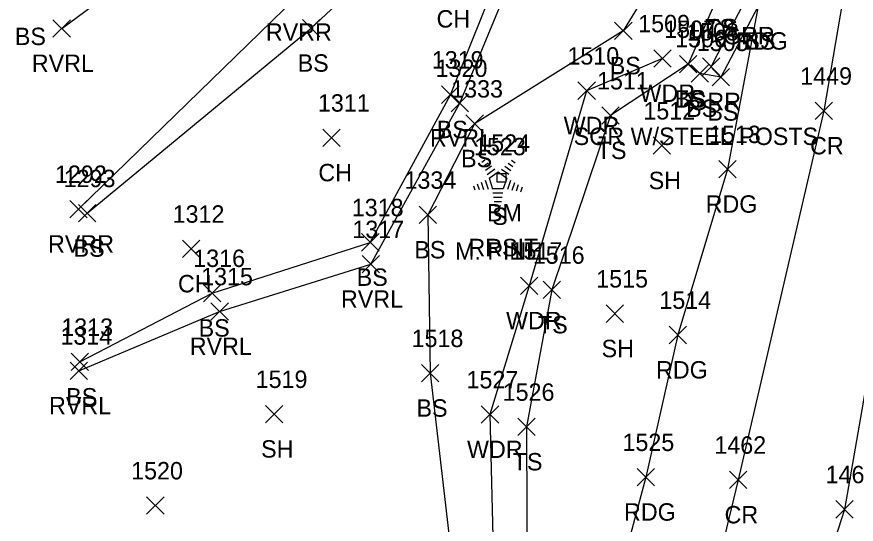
# Model space of a CAD drawing. Extents: x 1678553 to 1680768, y 787260 to 792325.
# Drawn here: x 1678590.7 to 1678687.1, y 787425.2 to 787483.5 of the extents above; entities that cross this region are included whole.
import ezdxf

# ---------------------------------------------------------------- set-up
doc = ezdxf.new("R2010")
doc.units = 0
for name, color, linetype in [('C_A', 7, 'Continuous'), ('C_C', 7, 'Continuous'), ('C_I', 7, 'Continuous'), ('CPBM', 7, 'Continuous'), ('L_A', 7, 'Continuous'), ('L_C', 7, 'Continuous'), ('L_I', 7, 'Continuous'), ('L_TIC', 7, 'Continuous'), ('LAWA', 7, 'Continuous'), ('LAWE', 7, 'Continuous'), ('LELB', 7, 'Continuous'), ('LTC', 7, 'Continuous'), ('P_A', 7, 'Continuous'), ('P_I', 7, 'Continuous'), ('P_TIC', 7, 'Continuous'), ('PEU', 7, 'Continuous'), ('PRC', 7, 'Continuous'), ('R_A', 7, 'Continuous'), ('R_C', 7, 'Continuous'), ('R_I', 7, 'Continuous'), ('R_TIC', 7, 'Continuous'), ('RGR', 7, 'Continuous')]:
    doc.layers.add(name, color=color, linetype=linetype)

msp = doc.modelspace()

# ---------------------------------------------------------------- linework, layer by layer
at = {"layer": 'CPBM'}
for p, q in [((1678645.899, 787464.531), (1678645.899, 787465.531)), ((1678645.899, 787465.531), (1678646.899, 787465.531)), ((1678646.402, 787465.032), (1678646.402, 787465.032)), ((1678646.402, 787465.032), (1678646.402, 787465.032)), ((1678646.899, 787465.531), (1678646.899, 787464.531)), ((1678646.899, 787464.531), (1678645.899, 787464.531))]:
    msp.add_line(p, q, dxfattribs=at)
at = {"layer": 'L_TIC'}
for points in [[(1678594.847, 787481.205), (1678596.847, 787483.205)], [(1678596.847, 787481.205), (1678594.847, 787483.205)], [(1678623.516, 787481.228), (1678625.516, 787483.228)], [(1678625.516, 787481.228), (1678623.516, 787483.228)], [(1678659.381, 787480.936), (1678661.381, 787482.936)], [(1678661.381, 787480.936), (1678659.381, 787482.936)], [(1678663.875, 787477.76), (1678665.875, 787479.76)], [(1678665.875, 787477.76), (1678663.875, 787479.76)], [(1678666.842, 787477.106), (1678668.842, 787479.106)], [(1678668.842, 787477.106), (1678666.842, 787479.106)], [(1678666.842, 787477.106), (1678668.842, 787479.106)], [(1678668.842, 787477.106), (1678666.842, 787479.106)], [(1678668.159, 787476.034), (1678670.159, 787478.034)], [(1678670.159, 787476.034), (1678668.159, 787478.034)], [(1678670.596, 787475.604), (1678672.596, 787477.604)], [(1678672.596, 787475.604), (1678670.596, 787477.604)], [(1678639.506, 787473.592), (1678641.506, 787475.592)], [(1678641.506, 787473.592), (1678639.506, 787475.592)], [(1678655.167, 787474.049), (1678657.167, 787476.049)], [(1678657.167, 787474.049), (1678655.167, 787476.049)], [(1678640.597, 787472.632), (1678642.597, 787474.632)], [(1678642.597, 787472.632), (1678640.597, 787474.632)], [(1678657.92, 787471.197), (1678659.92, 787473.197)], [(1678659.92, 787471.197), (1678657.92, 787473.197)], [(1678642.296, 787470.259), (1678644.296, 787472.259)], [(1678644.296, 787470.259), (1678642.296, 787472.259)], [(1678625.85, 787468.643), (1678627.85, 787470.643)], [(1678627.85, 787468.643), (1678625.85, 787470.643)], [(1678663.811, 787467.739), (1678665.811, 787469.739)], [(1678665.811, 787467.739), (1678663.811, 787469.739)], [(1678596.765, 787460.452), (1678598.765, 787462.452)], [(1678598.765, 787460.452), (1678596.765, 787462.452)], [(1678597.771, 787459.97), (1678599.771, 787461.97)], [(1678599.771, 787459.97), (1678597.771, 787461.97)], [(1678636.927, 787459.78), (1678638.927, 787461.78)], [(1678638.927, 787459.78), (1678636.927, 787461.78)], [(1678630.307, 787456.627), (1678632.307, 787458.627)], [(1678632.307, 787456.627), (1678630.307, 787458.627)], [(1678609.719, 787455.881), (1678611.719, 787457.881)], [(1678611.719, 787455.881), (1678609.719, 787457.881)], [(1678630.371, 787454.115), (1678632.371, 787456.115)], [(1678632.371, 787454.115), (1678630.371, 787456.115)], [(1678648.547, 787451.644), (1678650.547, 787453.644)], [(1678650.547, 787451.644), (1678648.547, 787453.644)], [(1678612.143, 787450.796), (1678614.143, 787452.796)], [(1678614.143, 787450.796), (1678612.143, 787452.796)], [(1678651.163, 787451.167), (1678653.163, 787453.167)], [(1678653.163, 787451.167), (1678651.163, 787453.167)], [(1678612.996, 787448.694), (1678614.996, 787450.694)], [(1678614.996, 787448.694), (1678612.996, 787450.694)], [(1678658.396, 787448.434), (1678660.396, 787450.434)], [(1678660.396, 787448.434), (1678658.396, 787450.434)], [(1678596.927, 787442.886), (1678598.927, 787444.886)], [(1678598.927, 787442.886), (1678596.927, 787444.886)], [(1678596.83, 787441.87), (1678598.83, 787443.87)], [(1678598.83, 787441.87), (1678596.83, 787443.87)], [(1678637.178, 787441.595), (1678639.178, 787443.595)], [(1678639.178, 787441.595), (1678637.178, 787443.595)], [(1678619.271, 787436.896), (1678621.271, 787438.896)], [(1678621.271, 787436.896), (1678619.271, 787438.896)], [(1678644.057, 787436.849), (1678646.057, 787438.849)], [(1678646.057, 787436.849), (1678644.057, 787438.849)], [(1678648.267, 787435.424), (1678650.267, 787437.424)], [(1678650.267, 787435.424), (1678648.267, 787437.424)], [(1678605.605, 787426.393), (1678607.605, 787428.393)], [(1678607.605, 787426.393), (1678605.605, 787428.393)]]:
    msp.add_lwpolyline(points, dxfattribs=at)
at = {"layer": 'LAWA'}
msp.add_lwpolyline([(1678664.875, 787478.76), (1678656.167, 787475.049), (1678649.547, 787452.644), (1678645.057, 787437.849), (1678645.533, 787417.534), (1678643.935, 787403.039), (1678640.142, 787385.556), (1678638.679, 787382.048), (1678636.341, 787358.012), (1678630.002, 787335.833), (1678617.261, 787305.351), (1678619.256, 787283.598)], dxfattribs=at)
at = {"layer": 'LAWE'}
for points in [[(1678597.83, 787442.87), (1678613.996, 787449.694), (1678631.371, 787455.115), (1678641.597, 787473.632), (1678648.099, 787489.375), (1678652.594, 787500.479), (1678670.341, 787510.611)], [(1678595.847, 787482.205), (1678614.765, 787496.203), (1678629.827, 787500.16), (1678637.075, 787496.761)], [(1678597.765, 787461.452), (1678622.801, 787485.788), (1678637.075, 787496.761)]]:
    msp.add_lwpolyline(points, dxfattribs=at)
at = {"layer": 'LELB'}
for points in [[(1678680.77, 787518.059), (1678676.295, 787498.712), (1678671.376, 787486.283), (1678667.842, 787478.106), (1678658.92, 787472.197), (1678652.163, 787452.167), (1678649.267, 787436.424), (1678649.323, 787416.121), (1678648.829, 787401.973), (1678646.777, 787382.688), (1678641.038, 787357.729), (1678634.181, 787333.529), (1678626.232, 787302.071), (1678622.908, 787282.585)], [(1678597.927, 787443.886), (1678613.143, 787451.796), (1678631.307, 787457.627), (1678640.506, 787474.592), (1678646.468, 787489.445), (1678651.341, 787501.275), (1678669.621, 787510.644)], [(1678670.341, 787510.611), (1678668.529, 787502.631), (1678666.357, 787491.771), (1678660.381, 787481.936), (1678643.296, 787471.259), (1678637.927, 787460.78), (1678638.178, 787442.595), (1678641.032, 787418.209), (1678640.004, 787400.912), (1678637.638, 787392.163), (1678640.142, 787385.556), (1678638.302, 787358.255), (1678630.002, 787335.833)], [(1678598.771, 787460.97), (1678624.516, 787482.228), (1678639.243, 787496.026)], [(1678675.858, 787484.768), (1678671.596, 787476.604), (1678669.159, 787477.034), (1678667.842, 787478.106)]]:
    msp.add_lwpolyline(points, dxfattribs=at)
at = {"layer": 'LTC'}
for p, q in [((1678644.116, 787466.838), (1678644.471, 787467.095)), ((1678647.515, 787467.078), (1678647.934, 787466.774)), ((1678644.326, 787466.372), (1678644.855, 787466.757)), ((1678644.536, 787465.907), (1678645.239, 787466.418)), ((1678644.745, 787465.441), (1678645.624, 787466.079)), ((1678646.401, 787466.033), (1678647.211, 787465.445)), ((1678646.773, 787466.382), (1678647.452, 787465.888)), ((1678647.144, 787466.73), (1678647.693, 787466.331)), ((1678644.97, 787464.986), (1678645.981, 787465.72)), ((1678644.97, 787464.986), (1678645.357, 787463.792)), ((1678645.981, 787465.72), (1678646.979, 787464.995)), ((1678646.979, 787464.995), (1678646.587, 787463.792)), ((1678643.149, 787464.117), (1678643.301, 787463.649)), ((1678643.604, 787464.334), (1678643.816, 787463.682)), ((1678644.06, 787464.55), (1678644.331, 787463.715)), ((1678644.515, 787464.767), (1678644.846, 787463.747)), ((1678647.416, 787464.725), (1678647.078, 787463.685)), ((1678647.861, 787464.474), (1678647.573, 787463.59)), ((1678648.305, 787464.224), (1678648.068, 787463.495)), ((1678648.749, 787463.974), (1678648.563, 787463.4)), ((1678646.587, 787463.792), (1678645.357, 787463.792)), ((1678646.549, 787463.292), (1678645.404, 787463.292)), ((1678646.465, 787462.792), (1678645.477, 787462.792)), ((1678646.381, 787462.292), (1678645.55, 787462.292)), ((1678646.298, 787461.792), (1678645.623, 787461.792))]:
    msp.add_line(p, q, dxfattribs=at)
at = {"layer": 'P_TIC'}
for points in [[(1678682.409, 787471.735), (1678684.409, 787473.735)], [(1678684.409, 787471.735), (1678682.409, 787473.735)], [(1678671.353, 787465.03), (1678673.353, 787467.03)], [(1678673.353, 787465.03), (1678671.353, 787467.03)], [(1678665.651, 787445.983), (1678667.651, 787447.983)], [(1678667.651, 787445.983), (1678665.651, 787447.983)], [(1678661.975, 787429.653), (1678663.975, 787431.653)], [(1678663.975, 787429.653), (1678661.975, 787431.653)], [(1678672.582, 787429.342), (1678674.582, 787431.342)], [(1678674.582, 787429.342), (1678672.582, 787431.342)], [(1678684.799, 787425.952), (1678686.799, 787427.952)], [(1678686.799, 787425.952), (1678684.799, 787427.952)]]:
    msp.add_lwpolyline(points, dxfattribs=at)
at = {"layer": 'PEU'}
for points in [[(1678701.084, 787523.46), (1678691.863, 787521.675), (1678683.928, 787520.501), (1678679.423, 787498.085), (1678675.858, 787484.768), (1678672.353, 787466.03), (1678666.651, 787446.983), (1678662.975, 787430.653), (1678658.139, 787412.595), (1678657.115, 787400.242), (1678651.997, 787380.889), (1678646.796, 787355.993), (1678640.868, 787332.433), (1678631.508, 787300.964), (1678626.743, 787281.591)], [(1678701.084, 787523.46), (1678699.331, 787512.572), (1678697.82, 787495.037), (1678694.118, 787469.827), (1678689.971, 787450.935), (1678685.799, 787426.952), (1678675.551, 787395.19), (1678665.556, 787365.837), (1678662.398, 787349.046), (1678655.839, 787321.611), (1678650.229, 787298.04), (1678645.331, 787276.771)]]:
    msp.add_lwpolyline(points, dxfattribs=at)
at = {"layer": 'PRC'}
msp.add_lwpolyline([(1678691.863, 787521.675), (1678687.471, 787496.537), (1678683.409, 787472.735), (1678673.582, 787430.342), (1678667.066, 787403.394), (1678661.63, 787379.176), (1678654.8, 787353.827), (1678646.933, 787323.808), (1678641.795, 787300.306), (1678636.187, 787278.722)], dxfattribs=at)
at = {"layer": 'R_TIC'}
for points in [[(1678669.471, 787476.811), (1678671.471, 787478.811)], [(1678671.471, 787476.811), (1678669.471, 787478.811)]]:
    msp.add_lwpolyline(points, dxfattribs=at)
at = {"layer": 'RGR'}
msp.add_lwpolyline([(1678683.363, 787519.815), (1678678.582, 787498.569), (1678674.343, 787485.377), (1678670.471, 787477.811)], dxfattribs=at)

# ---------------------------------------------------------------- texts
at = {"layer": 'C_A'}
msp.add_text('BM', height=2, dxfattribs=at).set_placement((1678644.717, 787460.032))
at = {"layer": 'C_C'}
msp.add_text('RRSIT', height=2, dxfattribs=at).set_placement((1678642.583, 787456.032))
at = {"layer": 'C_I'}
msp.add_text('1524', height=2, dxfattribs=at).set_placement((1678643.709, 787468.032))
at = {"layer": 'L_A'}
for s, p in [('CH', (1678638.92, 787482.303)), ('TS', (1678669.786, 787481.283)), ('CS', (1678669.817, 787481.283)), ('BS', (1678590.468, 787480.289)), ('RVRR', (1678619.313, 787480.788)), ('BS', (1678674.299, 787479.768)), ('RVRL', (1678592.413, 787477.205)), ('BS', (1678622.957, 787477.228)), ('BS', (1678658.822, 787476.936)), ('WDR', (1678662.237, 787473.76)), ('TS', (1678666.252, 787473.106)), ('BS', (1678666.283, 787473.106)), ('BS', (1678667.6, 787472.034)), ('BS', (1678670.037, 787471.604)), ('WDR', (1678653.529, 787470.049)), ('BS', (1678638.947, 787469.592)), ('RVRL', (1678638.164, 787468.632)), ('TS', (1678657.329, 787467.197)), ('BS', (1678641.737, 787466.259)), ('CH', (1678625.338, 787464.643)), ('SH', (1678663.299, 787463.739)), ('S', (1678645.307, 787459.63)), ('RVRR', (1678594.277, 787456.452)), ('BS', (1678597.212, 787455.97)), ('BS', (1678636.368, 787455.78)), ('BS', (1678629.748, 787452.627)), ('CH', (1678609.207, 787451.881)), ('RVRL', (1678627.938, 787450.115)), ('WDR', (1678646.909, 787447.644)), ('BS', (1678611.584, 787446.796)), ('TS', (1678650.573, 787447.167)), ('RVRL', (1678610.563, 787444.694)), ('SH', (1678657.884, 787444.434)), ('BS', (1678596.368, 787438.886)), ('RVRL', (1678594.397, 787437.87)), ('BS', (1678636.619, 787437.595)), ('SH', (1678618.759, 787432.896)), ('WDR', (1678642.419, 787432.849)), ('TS', (1678647.676, 787431.424))]:
    msp.add_text(s, height=2, dxfattribs=at).set_placement(p)
at = {"layer": 'L_C'}
msp.add_text('M. PINE', height=2, dxfattribs=at).set_placement((1678641.04, 787455.63))
at = {"layer": 'L_I'}
for s, p in [('1509', (1678662.095, 787481.76)), ('1507', (1678665.071, 787481.106)), ('1507', (1678665.071, 787481.106)), ('1506', (1678666.332, 787480.034)), ('1505', (1678668.825, 787479.604)), ('1319', (1678638.373, 787477.592)), ('1510', (1678653.955, 787478.049)), ('1320', (1678638.817, 787476.632)), ('1511', (1678657.361, 787475.197)), ('1333', (1678640.603, 787474.259)), ('1311', (1678625.291, 787472.643)), ('1512', (1678662.685, 787471.739)), ('1523', (1678643.229, 787467.63)), ('1292', (1678595.072, 787464.452)), ('1293', (1678596.078, 787463.97)), ('1334', (1678635.235, 787463.78)), ('1318', (1678629.181, 787460.627)), ('1312', (1678608.593, 787459.881)), ('1317', (1678629.245, 787458.115)), ('1517', (1678647.421, 787455.644)), ('1316', (1678610.962, 787454.796)), ('1516', (1678649.982, 787455.167)), ('1315', (1678611.87, 787452.694)), ('1515', (1678657.27, 787452.434)), ('1313', (1678595.802, 787446.886)), ('1314', (1678595.704, 787445.87)), ('1518', (1678636.053, 787445.595)), ('1519', (1678618.138, 787440.896)), ('1527', (1678642.364, 787440.849)), ('1526', (1678646.519, 787439.424)), ('1520', (1678603.825, 787430.393))]:
    msp.add_text(s, height=2, dxfattribs=at).set_placement(p)
at = {"layer": 'LTC'}
msp.add_text('.', height=1.037, rotation=270, dxfattribs=at).set_placement((1678645.864, 787464.734))
at = {"layer": 'P_A'}
for s, p in [('RDG', (1678673.346, 787479.768)), ('CR', (1678681.842, 787467.735)), ('RDG', (1678669.841, 787461.03)), ('RDG', (1678664.139, 787441.983)), ('RDG', (1678660.464, 787425.653)), ('CR', (1678672.015, 787425.342))]:
    msp.add_text(s, height=2, dxfattribs=at).set_placement(p)
at = {"layer": 'P_I'}
for s, p in [('1449', (1678680.708, 787475.735)), ('1513', (1678670.228, 787469.03)), ('1514', (1678664.525, 787449.983)), ('1525', (1678660.283, 787433.653)), ('1462', (1678670.842, 787433.342)), ('1461', (1678683.626, 787429.952))]:
    msp.add_text(s, height=2, dxfattribs=at).set_placement(p)
at = {"layer": 'R_A'}
for p in [(1678671.832, 787480.377), (1678667.959, 787472.811)]:
    msp.add_text('GRR', height=2, dxfattribs=at).set_placement(p)
at = {"layer": 'R_C'}
msp.add_text('SGR W/STEEL POSTS', height=2, dxfattribs=at).set_placement((1678654.676, 787468.811))
at = {"layer": 'R_I'}
msp.add_text('1508', height=2, dxfattribs=at).set_placement((1678667.7, 787480.811))

doc.saveas('drawing.dxf')
